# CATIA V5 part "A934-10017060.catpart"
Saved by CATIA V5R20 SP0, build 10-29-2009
Part number: A934-10017060
Source: Unknown
Property "A": "60.000"
Property "ARTICLENO": "A934-10017060"
Property "B": "30.000"
Property "BOMINFO": "A934-10017060"
Property "CODE": "A934-10017060"
Property "L": "170.000"
Property "L1": "127.860"
Property "LINA": "A934-10017060"
Property "NB": "A934-10017060"
Property "NBSYN": "$CODE."
Property "NN": "A934"
Property "NT": "VDI 3357 H-Type Cam Drivers, self-lubricating"
Property "SUPPLIER": "CF"
Property "T": "60.000"
Property "W": "100.000"
Bounding box of the stored display mesh (mm): x 0 to 170, y 0 to 60, z -100 to 0
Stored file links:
  C:\Users\Utente\Desktop\3D files A934\A934-10017060.catpart
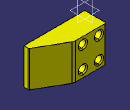
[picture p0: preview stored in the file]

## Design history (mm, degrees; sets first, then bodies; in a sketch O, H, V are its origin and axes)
Body1 "Geometry.1" (main body)
  Solid1 "A934-10017060.catpart": solid without history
